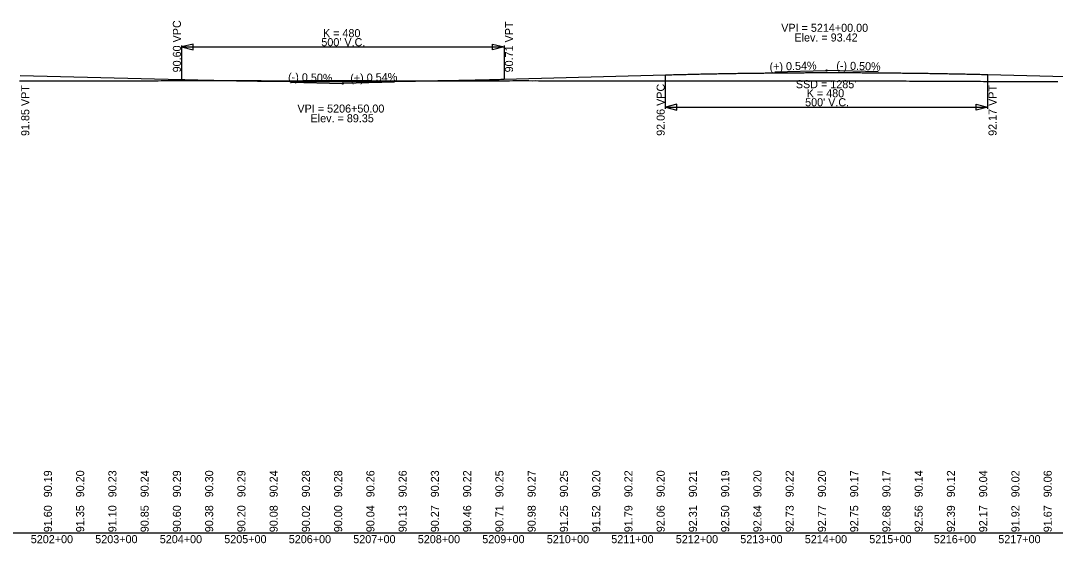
# Model space of a CAD drawing. Extents: x 2147288 to 2220488, y 740833 to 759333.
# Drawn here: x 2152532 to 2154136, y 758067 to 758878 of the extents above; entities that cross this region are included whole.
import ezdxf

# ---------------------------------------------------------------- set-up
doc = ezdxf.new("R2010")
doc.units = 0
for name, color, linetype in [('RD_DDB_GradeTX', 7, 'Continuous'), ('RD_DDB_Profile_EX', 7, 'Continuous'), ('RD_DDB_Profile_Lbl', 7, 'Continuous'), ('RD_DDB_Profile_PR', 7, 'Continuous'), ('RD_DDB_StaTX', 7, 'Continuous'), ('RD_DDB_StripGrade', 7, 'Continuous'), ('RD_DDB_VCLbl', 7, 'Continuous'), ('RD_GPK_Profile_Cell', 7, 'Continuous')]:
    doc.layers.add(name, color=color, linetype=linetype)

msp = doc.modelspace()

# ---------------------------------------------------------------- linework, layer by layer
at = {"layer": 'RD_DDB_GradeTX'}
for p, q in [((2153701.1, 758798.4), (2153780.1, 758800.5)), ((2153861.1, 758798.5), (2153782.1, 758800.5)), ((2152951.1, 758782.2), (2153030.1, 758780.2)), ((2153111.1, 758782.3), (2153032.1, 758780.2))]:
    msp.add_line(p, q, dxfattribs=at)
for centre in [(2153781.1, 758800.5), (2153031.1, 758780.2)]:
    msp.add_circle(centre, 1, dxfattribs=at)
at = {"layer": 'RD_DDB_Profile_EX'}
for points in [[(2152529.6, 758784.6), (2152534.6, 758784.5)], [(2152534.6, 758784.5), (2152539.6, 758784.5), (2152544.6, 758784.5), (2152549.6, 758784.5), (2152554.6, 758784.5), (2152559.6, 758784.5), (2152564.6, 758784.4), (2152569.6, 758784.4), (2152574.6, 758784.4), (2152579.6, 758784.4), (2152584.6, 758784.4), (2152589.6, 758784.4), (2152594.6, 758784.4), (2152599.6, 758784.4), (2152604.6, 758784.3), (2152609.6, 758784.3), (2152614.6, 758784.4), (2152619.6, 758784.4), (2152624.6, 758784.4), (2152629.6, 758784.4), (2152634.6, 758784.4), (2152639.6, 758784.4), (2152644.6, 758784.4), (2152649.6, 758784.5), (2152654.6, 758784.5), (2152659.6, 758784.5), (2152664.6, 758784.5), (2152669.6, 758784.5), (2152674.6, 758784.5), (2152679.6, 758784.6), (2152684.6, 758784.6), (2152689.6, 758784.6), (2152694.6, 758784.6), (2152699.6, 758784.6), (2152704.6, 758784.6), (2152709.6, 758784.6), (2152714.6, 758784.6), (2152719.6, 758784.6), (2152724.6, 758784.6), (2152729.6, 758784.6), (2152734.6, 758784.7), (2152739.6, 758784.7), (2152744.6, 758784.7), (2152749.6, 758784.8), (2152754.6, 758784.8), (2152759.6, 758784.8), (2152764.6, 758784.8), (2152769.6, 758784.8), (2152774.6, 758784.9), (2152779.6, 758784.9), (2152784.6, 758784.9), (2152789.6, 758784.9), (2152794.6, 758784.9), (2152799.6, 758784.9), (2152804.6, 758784.9), (2152809.6, 758784.9), (2152814.6, 758784.9), (2152819.6, 758784.9), (2152824.6, 758784.9), (2152829.6, 758784.9), (2152834.6, 758784.9), (2152839.6, 758784.9), (2152844.6, 758784.9), (2152849.6, 758784.9), (2152854.6, 758784.9), (2152859.6, 758784.9), (2152864.6, 758784.9), (2152869.6, 758784.9), (2152874.6, 758784.9), (2152879.6, 758784.9), (2152884.6, 758784.9), (2152889.6, 758784.9), (2152894.6, 758784.8), (2152899.6, 758784.8), (2152904.6, 758784.8), (2152909.6, 758784.7), (2152914.6, 758784.7), (2152919.6, 758784.7), (2152924.6, 758784.7), (2152929.6, 758784.6), (2152934.6, 758784.7), (2152939.6, 758784.7), (2152944.6, 758784.7), (2152949.6, 758784.7), (2152954.6, 758784.7), (2152959.6, 758784.7), (2152964.6, 758784.7), (2152969.6, 758784.8), (2152974.6, 758784.8), (2152979.6, 758784.8), (2152984.6, 758784.9), (2152989.6, 758784.9), (2152994.6, 758784.9), (2152999.6, 758784.9), (2153004.6, 758784.9), (2153009.6, 758785), (2153014.6, 758784.9), (2153019.6, 758784.9), (2153024.6, 758784.9), (2153029.6, 758784.8), (2153034.6, 758784.9)], [(2153034.6, 758784.9), (2153039.6, 758784.9), (2153044.6, 758784.8), (2153049.6, 758784.9), (2153054.6, 758784.9), (2153059.6, 758784.9), (2153064.6, 758784.9), (2153069.6, 758784.9), (2153074.6, 758784.8), (2153079.6, 758784.7), (2153084.6, 758784.7), (2153089.6, 758784.7), (2153094.6, 758784.7), (2153099.6, 758784.7), (2153104.6, 758784.7), (2153109.6, 758784.7), (2153114.6, 758784.7), (2153119.6, 758784.7), (2153124.6, 758784.7), (2153129.6, 758784.7), (2153134.6, 758784.7), (2153139.6, 758784.7), (2153144.6, 758784.7), (2153149.6, 758784.7), (2153154.6, 758784.7), (2153159.6, 758784.6), (2153164.6, 758784.6), (2153169.6, 758784.5), (2153174.6, 758784.5), (2153179.6, 758784.6), (2153184.6, 758784.6), (2153189.6, 758784.6), (2153194.6, 758784.6), (2153199.6, 758784.6), (2153204.6, 758784.6), (2153209.6, 758784.6), (2153214.6, 758784.6), (2153219.6, 758784.6), (2153224.6, 758784.6), (2153229.6, 758784.5), (2153234.6, 758784.5), (2153239.6, 758784.4), (2153244.6, 758784.4), (2153249.6, 758784.5), (2153254.6, 758784.5), (2153259.6, 758784.6), (2153264.6, 758784.6), (2153269.6, 758784.6), (2153274.6, 758784.6), (2153279.6, 758784.7), (2153284.6, 758784.7), (2153289.6, 758784.7), (2153294.6, 758784.8), (2153299.6, 758784.8), (2153304.6, 758784.8), (2153309.6, 758784.9), (2153314.6, 758784.8), (2153319.6, 758784.8), (2153324.6, 758784.7), (2153329.6, 758784.8), (2153334.6, 758784.7), (2153339.6, 758784.7), (2153344.6, 758784.7), (2153349.6, 758784.7), (2153354.6, 758784.7), (2153359.6, 758784.7), (2153364.6, 758784.7), (2153369.6, 758784.7), (2153374.6, 758784.7), (2153379.6, 758784.7), (2153384.6, 758784.6), (2153389.6, 758784.6), (2153394.6, 758784.6), (2153399.6, 758784.6), (2153404.6, 758784.5), (2153409.6, 758784.5), (2153414.6, 758784.5), (2153419.6, 758784.4), (2153424.6, 758784.4), (2153429.6, 758784.4), (2153434.6, 758784.4), (2153439.6, 758784.4), (2153444.6, 758784.4), (2153449.6, 758784.5), (2153454.6, 758784.5), (2153459.6, 758784.5), (2153464.6, 758784.5), (2153469.6, 758784.5), (2153474.6, 758784.6), (2153479.6, 758784.5), (2153484.6, 758784.5), (2153489.6, 758784.5), (2153494.6, 758784.5), (2153499.6, 758784.5), (2153504.6, 758784.4), (2153509.6, 758784.4), (2153514.6, 758784.4), (2153519.6, 758784.4), (2153524.6, 758784.4), (2153529.6, 758784.4), (2153534.6, 758784.4)], [(2153534.6, 758784.4), (2153539.6, 758784.4), (2153544.6, 758784.4), (2153549.6, 758784.4), (2153554.6, 758784.4), (2153559.6, 758784.4), (2153564.6, 758784.4), (2153569.6, 758784.4), (2153574.6, 758784.4), (2153579.6, 758784.4), (2153584.6, 758784.5), (2153589.6, 758784.5), (2153594.6, 758784.5), (2153599.6, 758784.5), (2153604.6, 758784.4), (2153609.6, 758784.4), (2153614.6, 758784.4), (2153619.6, 758784.4), (2153624.6, 758784.4), (2153629.6, 758784.4), (2153634.6, 758784.4), (2153639.6, 758784.4), (2153644.6, 758784.4), (2153649.6, 758784.4), (2153654.6, 758784.4), (2153659.6, 758784.4), (2153664.6, 758784.5), (2153669.6, 758784.5), (2153674.6, 758784.4), (2153679.6, 758784.4), (2153684.6, 758784.4), (2153689.6, 758784.5), (2153694.6, 758784.4), (2153699.6, 758784.4), (2153704.6, 758784.4), (2153709.6, 758784.4), (2153714.6, 758784.4), (2153719.6, 758784.4), (2153724.6, 758784.4), (2153729.6, 758784.5), (2153734.6, 758784.7), (2153739.6, 758784.7), (2153744.6, 758784.7), (2153749.6, 758784.7), (2153754.6, 758784.6), (2153759.6, 758784.6), (2153764.6, 758784.5), (2153769.6, 758784.5), (2153774.6, 758784.5), (2153779.6, 758784.4), (2153784.6, 758784.4), (2153789.6, 758784.3), (2153794.6, 758784.3), (2153799.6, 758784.2), (2153804.6, 758784.3), (2153809.6, 758784.3), (2153814.6, 758784.3), (2153819.6, 758784.3), (2153824.6, 758784.3), (2153829.6, 758784.3), (2153834.6, 758784.3), (2153839.6, 758784.3), (2153844.6, 758784.3), (2153849.6, 758784.3), (2153854.6, 758784.3), (2153859.6, 758784.3), (2153864.6, 758784.3), (2153869.6, 758784.3), (2153874.6, 758784.3), (2153879.6, 758784.3), (2153884.6, 758784.3), (2153889.6, 758784.3), (2153894.6, 758784.3), (2153899.6, 758784.3), (2153904.6, 758784.3), (2153909.6, 758784.2), (2153914.6, 758784.2), (2153919.6, 758784.2), (2153924.6, 758784.2), (2153929.6, 758784.2), (2153934.6, 758784.1), (2153939.6, 758784.1), (2153944.6, 758784.1), (2153949.6, 758784.1), (2153954.6, 758784.1), (2153959.6, 758784), (2153964.6, 758784), (2153969.6, 758784), (2153974.6, 758784), (2153979.6, 758784), (2153984.6, 758784), (2153989.6, 758784), (2153994.6, 758784), (2153999.6, 758783.9), (2154004.6, 758783.9), (2154009.6, 758783.9), (2154014.6, 758783.8), (2154019.6, 758783.8), (2154024.6, 758783.7), (2154029.6, 758783.7), (2154034.6, 758783.6)], [(2154034.6, 758783.6), (2154039.6, 758783.6), (2154044.6, 758783.6), (2154049.6, 758783.6), (2154054.6, 758783.6), (2154059.6, 758783.6), (2154064.6, 758783.6), (2154069.6, 758783.5), (2154074.6, 758783.5), (2154079.6, 758783.5), (2154084.6, 758783.5), (2154089.6, 758783.5), (2154094.6, 758783.6), (2154099.6, 758783.6), (2154104.6, 758783.6), (2154109.6, 758783.6), (2154114.6, 758783.7), (2154119.6, 758783.7), (2154124.6, 758783.7), (2154129.6, 758783.7), (2154134.6, 758783.7), (2154139.6, 758783.7)]]:
    msp.add_lwpolyline(points, dxfattribs=at)
at = {"layer": 'RD_DDB_Profile_PR'}
for p, q in [((2152531.1, 758792.7), (2152781.1, 758786.4)), ((2153281.1, 758787), (2153531.1, 758793.7)), ((2154031.1, 758794.3), (2154231.1, 758789.3))]:
    msp.add_line(p, q, dxfattribs=at)
for points in [[(2152781.1, 758786.4), (2152791.1, 758786.2), (2152801.1, 758785.9), (2152811.1, 758785.7), (2152821.1, 758785.5), (2152831.1, 758785.3), (2152841.1, 758785.1), (2152851.1, 758784.9), (2152861.1, 758784.8), (2152871.1, 758784.6), (2152881.1, 758784.4), (2152891.1, 758784.3), (2152901.1, 758784.2), (2152911.1, 758784.1), (2152921.1, 758783.9), (2152931.1, 758783.9), (2152941.1, 758783.8), (2152951.1, 758783.7), (2152961.1, 758783.6), (2152971.1, 758783.6), (2152981.1, 758783.5), (2152991.1, 758783.5), (2153001.1, 758783.5), (2153011.1, 758783.4), (2153021.1, 758783.4), (2153031.1, 758783.4), (2153041.1, 758783.5), (2153051.1, 758783.5), (2153061.1, 758783.5), (2153071.1, 758783.6), (2153081.1, 758783.6), (2153091.1, 758783.7), (2153101.1, 758783.8), (2153111.1, 758783.9), (2153121.1, 758784), (2153131.1, 758784.1), (2153141.1, 758784.2), (2153151.1, 758784.3), (2153161.1, 758784.5), (2153171.1, 758784.6), (2153181.1, 758784.8), (2153191.1, 758784.9), (2153201.1, 758785.1), (2153211.1, 758785.3), (2153221.1, 758785.5), (2153231.1, 758785.7), (2153241.1, 758786), (2153251.1, 758786.2), (2153261.1, 758786.4), (2153271.1, 758786.7), (2153281.1, 758787)], [(2153531.1, 758793.7), (2153541.1, 758794), (2153551.1, 758794.3), (2153561.1, 758794.5), (2153571.1, 758794.7), (2153581.1, 758795), (2153591.1, 758795.2), (2153601.1, 758795.4), (2153611.1, 758795.6), (2153621.1, 758795.8), (2153631.1, 758795.9), (2153641.1, 758796.1), (2153651.1, 758796.2), (2153661.1, 758796.4), (2153671.1, 758796.5), (2153681.1, 758796.6), (2153691.1, 758796.7), (2153701.1, 758796.8), (2153711.1, 758796.9), (2153721.1, 758797), (2153731.1, 758797.1), (2153741.1, 758797.1), (2153751.1, 758797.2), (2153761.1, 758797.2), (2153771.1, 758797.2), (2153781.1, 758797.3), (2153791.1, 758797.3), (2153801.1, 758797.3), (2153811.1, 758797.2), (2153821.1, 758797.2), (2153831.1, 758797.2), (2153841.1, 758797.1), (2153851.1, 758797.1), (2153861.1, 758797), (2153871.1, 758796.9), (2153881.1, 758796.8), (2153891.1, 758796.7), (2153901.1, 758796.6), (2153911.1, 758796.5), (2153921.1, 758796.4), (2153931.1, 758796.2), (2153941.1, 758796.1), (2153951.1, 758795.9), (2153961.1, 758795.8), (2153971.1, 758795.6), (2153981.1, 758795.4), (2153991.1, 758795.2), (2154001.1, 758795), (2154011.1, 758794.8), (2154021.1, 758794.5), (2154031.1, 758794.3)]]:
    msp.add_spline(points, degree=3, dxfattribs=at)
at = {"layer": 'RD_DDB_VCLbl'}
for p, q in [((2152781.1, 758839.5), (2152781.1, 758786.4)), ((2152781.1, 758837), (2153281.1, 758837)), ((2153281.1, 758839.5), (2153281.1, 758787)), ((2153531.1, 758741.2), (2153531.1, 758793.7)), ((2154031.1, 758741.2), (2154031.1, 758794.3)), ((2153531.1, 758743.7), (2154031.1, 758743.7))]:
    msp.add_line(p, q, dxfattribs=at)
for points in [[(2152799.1, 758841.5), (2152781.1, 758837), (2152799.1, 758832.5)], [(2153263.1, 758841.5), (2153281.1, 758837), (2153263.1, 758832.5)], [(2153549.1, 758748.2), (2153531.1, 758743.7), (2153549.1, 758739.2)], [(2154013.1, 758748.2), (2154031.1, 758743.7), (2154013.1, 758739.2)]]:
    msp.add_lwpolyline(points, close=True, dxfattribs=at)
at = {"layer": 'RD_GPK_Profile_Cell'}
msp.add_line((2148888.3, 758083.4), (2165888.3, 758083.4), dxfattribs=at)

# ---------------------------------------------------------------- texts
at = {"layer": 'RD_DDB_GradeTX'}
for s, rotation, p in [('(+) 0.54%', 1.5538, (2153692.8, 758800.1)), ('(-) 0.50%', 358.5679, (2153796, 758802.1)), ('(-) 0.50%', 358.5679, (2152946.1, 758784.3)), ('(+) 0.54%', 1.5538, (2153042.8, 758782.5))]:
    msp.add_text(s, height=12.5, rotation=rotation, dxfattribs=at).set_placement(p)
at = {"layer": 'RD_DDB_Profile_Lbl'}
for s, p in [('VPI = 5214+00.00', (2153710.7, 758860.5)), ('Elev. = 93.42', (2153731.2, 758845.5)), ('VPI = 5206+50.00', (2152960.7, 758735.2)), ('Elev. = 89.35', (2152981.1, 758720.2))]:
    msp.add_text(s, height=12.5, dxfattribs=at).set_placement(p)
at = {"layer": 'RD_DDB_StaTX'}
for s, p in [('5202+00', (2152547.3, 758067.2)), ('5203+00', (2152647.3, 758067.2)), ('5204+00', (2152747.3, 758067.2)), ('5205+00', (2152847.3, 758067.2)), ('5206+00', (2152947.3, 758067.2)), ('5207+00', (2153047.3, 758067.2)), ('5208+00', (2153147.3, 758067.2)), ('5209+00', (2153247.3, 758067.2)), ('5210+00', (2153347.3, 758067.2)), ('5211+00', (2153447.3, 758067.2)), ('5212+00', (2153547.3, 758067.2)), ('5213+00', (2153647.3, 758067.2)), ('5214+00', (2153747.3, 758067.2)), ('5215+00', (2153847.3, 758067.2)), ('5216+00', (2153947.3, 758067.2)), ('5217+00', (2154047.3, 758067.2))]:
    msp.add_text(s, height=12.5, dxfattribs=at).set_placement(p)
at = {"layer": 'RD_DDB_StripGrade'}
for s, p in [('90.60 VPC', (2152780.1, 758797.6)), ('90.71 VPT', (2153295, 758797.6)), ('91.85 VPT', (2152545, 758698.9)), ('92.06 VPC', (2153530.1, 758699.1)), ('92.17 VPT', (2154044.6, 758699.1)), ('90.19', (2152580.1, 758138.4)), ('90.20', (2152630.1, 758138.4)), ('90.23', (2152680.1, 758138.4)), ('90.24', (2152730.1, 758138.4)), ('90.29', (2152780.1, 758138.4)), ('90.30', (2152830.1, 758138.4)), ('90.29', (2152880.1, 758138.4)), ('90.24', (2152930.1, 758138.4)), ('90.28', (2152980.1, 758138.4)), ('90.28', (2153030.1, 758138.4)), ('90.26', (2153080.1, 758138.4)), ('90.26', (2153130.1, 758138.4)), ('90.23', (2153180.1, 758138.4)), ('90.22', (2153230.1, 758138.4)), ('90.25', (2153280.1, 758138.4)), ('90.27', (2153330.1, 758138.4)), ('90.25', (2153380.1, 758138.4)), ('90.20', (2153430.1, 758138.4)), ('90.22', (2153480.1, 758138.4)), ('90.20', (2153530.1, 758138.4)), ('90.21', (2153580.1, 758138.4)), ('90.19', (2153630.1, 758138.4)), ('90.20', (2153680.1, 758138.4)), ('90.22', (2153730.1, 758138.4)), ('90.20', (2153780.1, 758138.4)), ('90.17', (2153830.1, 758138.4)), ('90.17', (2153880.1, 758138.4)), ('90.14', (2153930.1, 758138.4)), ('90.12', (2153980.1, 758138.4)), ('90.04', (2154030.1, 758138.4)), ('90.02', (2154080.1, 758138.4)), ('90.06', (2154130.1, 758138.4)), ('91.60', (2152580.1, 758084.2)), ('91.35', (2152630.1, 758084.2)), ('91.10', (2152680.1, 758084.2)), ('90.85', (2152730.1, 758084.2)), ('90.60', (2152780.1, 758084.2)), ('90.38', (2152830.1, 758084.2)), ('90.20', (2152880.1, 758084.2)), ('90.08', (2152930.1, 758084.2)), ('90.02', (2152980.1, 758084.2)), ('90.00', (2153030.1, 758084.2)), ('90.04', (2153080.1, 758084.2)), ('90.13', (2153130.1, 758084.2)), ('90.27', (2153180.1, 758084.2)), ('90.46', (2153230.1, 758084.2)), ('90.71', (2153280.1, 758084.2)), ('90.98', (2153330.1, 758084.2)), ('91.25', (2153380.1, 758084.2)), ('91.52', (2153430.1, 758084.2)), ('91.79', (2153480.1, 758084.2)), ('92.06', (2153530.1, 758084.2)), ('92.31', (2153580.1, 758084.2)), ('92.50', (2153630.1, 758084.2)), ('92.64', (2153680.1, 758084.2)), ('92.73', (2153730.1, 758084.2)), ('92.77', (2153780.1, 758084.2)), ('92.75', (2153830.1, 758084.2)), ('92.68', (2153880.1, 758084.2)), ('92.56', (2153930.1, 758084.2)), ('92.39', (2153980.1, 758084.2)), ('92.17', (2154030.1, 758084.2)), ('91.92', (2154080.1, 758084.2)), ('91.67', (2154130.1, 758084.2))]:
    msp.add_text(s, height=12.5, rotation=90, dxfattribs=at).set_placement(p)
at = {"layer": 'RD_DDB_VCLbl'}
for s, p in [('K = 480', (2153000.3, 758852.2)), ("500' V.C.", (2152997.8, 758838.2)), ("SSD = 1285'", (2153733.4, 758773)), ('K = 480', (2153750.3, 758759)), ("500' V.C.", (2153747.8, 758745))]:
    msp.add_text(s, height=12.5, dxfattribs=at).set_placement(p)

doc.saveas('drawing.dxf')
